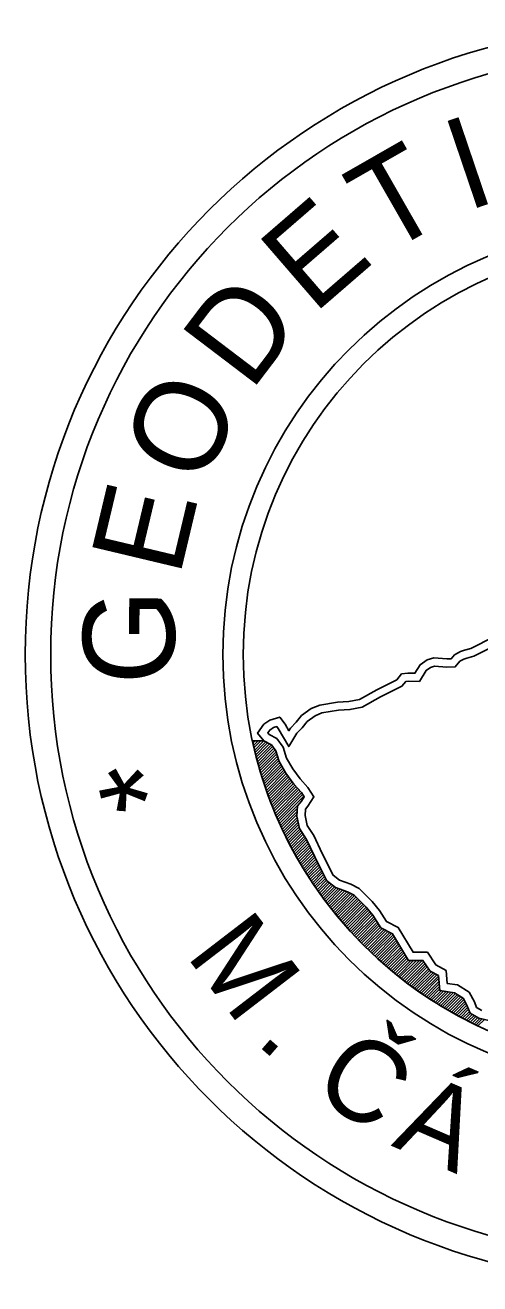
# Model space of a CAD drawing. Extents: x -820819 to -820609, y -1070301 to -1070004.
# Drawn here: x -820684.45 to -820678.53, y -1070186.61 to -1070170.22 of the extents above; entities that cross this region are included whole.
import ezdxf

# ---------------------------------------------------------------- set-up
doc = ezdxf.new("R2010")
doc.units = 0
doc.layers.add('Vrstva 63', color=7, linetype='Continuous')

msp = doc.modelspace()

# ---------------------------------------------------------------- linework, layer by layer
at = {"layer": 'Vrstva 63'}
for p, q in [((-820681.342, -1070179.542), (-820681.491, -1070179.541)), ((-820681.342, -1070179.542), (-820681.491, -1070179.541)), ((-820681.491, -1070179.541), (-820681.49, -1070179.541)), ((-820681.484, -1070179.572), (-820681.453, -1070179.541)), ((-820681.477, -1070179.603), (-820681.416, -1070179.541)), ((-820681.47, -1070179.633), (-820681.379, -1070179.542)), ((-820681.463, -1070179.664), (-820681.341, -1070179.542)), ((-820681.456, -1070179.694), (-820681.317, -1070179.555)), ((-820681.448, -1070179.724), (-820681.292, -1070179.568)), ((-820681.441, -1070179.754), (-820681.268, -1070179.581)), ((-820681.433, -1070179.784), (-820681.243, -1070179.594)), ((-820681.425, -1070179.813), (-820681.227, -1070179.615)), ((-820681.417, -1070179.843), (-820681.211, -1070179.637)), ((-820681.409, -1070179.872), (-820681.194, -1070179.658)), ((-820681.4, -1070179.901), (-820681.181, -1070179.683)), ((-820681.392, -1070179.931), (-820681.173, -1070179.711)), ((-820681.383, -1070179.959), (-820681.164, -1070179.74)), ((-820681.374, -1070179.988), (-820681.155, -1070179.769)), ((-820681.365, -1070180.017), (-820681.146, -1070179.798)), ((-820681.356, -1070180.046), (-820681.134, -1070179.823)), ((-820681.347, -1070180.074), (-820681.12, -1070179.847)), ((-820681.338, -1070180.102), (-820681.106, -1070179.871)), ((-820681.329, -1070180.13), (-820681.092, -1070179.894)), ((-820681.319, -1070180.158), (-820681.078, -1070179.918)), ((-820681.309, -1070180.186), (-820681.064, -1070179.941)), ((-820681.299, -1070180.214), (-820681.05, -1070179.965)), ((-820681.29, -1070180.242), (-820681.035, -1070179.987)), ((-820681.279, -1070180.269), (-820681.019, -1070180.009)), ((-820681.269, -1070180.297), (-820681.004, -1070180.031)), ((-820681.259, -1070180.324), (-820680.988, -1070180.053)), ((-820681.249, -1070180.351), (-820680.973, -1070180.075)), ((-820681.238, -1070180.378), (-820680.957, -1070180.097)), ((-820681.227, -1070180.405), (-820680.94, -1070180.118)), ((-820681.216, -1070180.432), (-820680.922, -1070180.137)), ((-820681.206, -1070180.458), (-820680.904, -1070180.157)), ((-820681.195, -1070180.485), (-820680.886, -1070180.176)), ((-820681.183, -1070180.511), (-820680.868, -1070180.196)), ((-820681.172, -1070180.538), (-820680.85, -1070180.216)), ((-820681.161, -1070180.564), (-820680.836, -1070180.239)), ((-820681.149, -1070180.59), (-820680.821, -1070180.262)), ((-820681.138, -1070180.616), (-820680.878, -1070180.356)), ((-820681.126, -1070180.642), (-820680.906, -1070180.422)), ((-820681.114, -1070180.667), (-820680.908, -1070180.462)), ((-820681.102, -1070180.693), (-820680.91, -1070180.501)), ((-820681.09, -1070180.719), (-820680.908, -1070180.537)), ((-820681.078, -1070180.744), (-820680.902, -1070180.568)), ((-820681.066, -1070180.769), (-820680.895, -1070180.599)), ((-820681.053, -1070180.794), (-820680.889, -1070180.63)), ((-820681.041, -1070180.82), (-820680.882, -1070180.661)), ((-820681.028, -1070180.845), (-820680.874, -1070180.69)), ((-820681.015, -1070180.869), (-820680.859, -1070180.713)), ((-820681.002, -1070180.894), (-820680.844, -1070180.735)), ((-820680.99, -1070180.919), (-820680.829, -1070180.758)), ((-820680.976, -1070180.943), (-820680.814, -1070180.781)), ((-820680.963, -1070180.968), (-820680.799, -1070180.804)), ((-820680.95, -1070180.992), (-820680.784, -1070180.826)), ((-820680.937, -1070181.016), (-820680.772, -1070180.852)), ((-820680.923, -1070181.04), (-820680.76, -1070180.877)), ((-820680.91, -1070181.064), (-820680.748, -1070180.903)), ((-820680.896, -1070181.088), (-820680.736, -1070180.928)), ((-820680.882, -1070181.112), (-820680.724, -1070180.954)), ((-820680.868, -1070181.136), (-820680.712, -1070180.979)), ((-820680.854, -1070181.159), (-820680.7, -1070181.005)), ((-820680.84, -1070181.183), (-820680.688, -1070181.031)), ((-820680.826, -1070181.206), (-820680.676, -1070181.056)), ((-820680.812, -1070181.229), (-820680.663, -1070181.081)), ((-820680.797, -1070181.253), (-820680.651, -1070181.106)), ((-820680.783, -1070181.276), (-820680.638, -1070181.131)), ((-820680.768, -1070181.299), (-820680.626, -1070181.156)), ((-820680.754, -1070181.322), (-820680.613, -1070181.181)), ((-820680.739, -1070181.344), (-820680.601, -1070181.207)), ((-820680.724, -1070181.367), (-820680.588, -1070181.232)), ((-820680.709, -1070181.39), (-820680.576, -1070181.257)), ((-820680.694, -1070181.412), (-820680.563, -1070181.282)), ((-820680.679, -1070181.435), (-820680.551, -1070181.307)), ((-820680.663, -1070181.457), (-820680.539, -1070181.332)), ((-820680.648, -1070181.479), (-820680.526, -1070181.357)), ((-820680.632, -1070181.501), (-820680.506, -1070181.375)), ((-820680.617, -1070181.523), (-820680.485, -1070181.391)), ((-820680.601, -1070181.545), (-820680.464, -1070181.407)), ((-820680.585, -1070181.567), (-820680.442, -1070181.424)), ((-820680.57, -1070181.589), (-820680.421, -1070181.44)), ((-820680.554, -1070181.61), (-820680.398, -1070181.455)), ((-820680.537, -1070181.632), (-820680.37, -1070181.464)), ((-820680.521, -1070181.653), (-820680.342, -1070181.474)), ((-820680.505, -1070181.674), (-820680.314, -1070181.483)), ((-820680.489, -1070181.696), (-820680.286, -1070181.493)), ((-820680.472, -1070181.717), (-820680.258, -1070181.503)), ((-820680.456, -1070181.738), (-820680.232, -1070181.514)), ((-820680.439, -1070181.759), (-820680.208, -1070181.527)), ((-820680.422, -1070181.78), (-820680.183, -1070181.54)), ((-820680.405, -1070181.8), (-820680.159, -1070181.554)), ((-820680.389, -1070181.821), (-820680.14, -1070181.573)), ((-820680.372, -1070181.841), (-820680.122, -1070181.592)), ((-820680.354, -1070181.862), (-820680.103, -1070181.611)), ((-820680.337, -1070181.882), (-820680.084, -1070181.63)), ((-820680.32, -1070181.903), (-820680.066, -1070181.648)), ((-820680.303, -1070181.923), (-820680.047, -1070181.667)), ((-820680.285, -1070181.943), (-820680.029, -1070181.686)), ((-820680.267, -1070181.963), (-820680.01, -1070181.705)), ((-820680.25, -1070181.983), (-820679.993, -1070181.726)), ((-820680.232, -1070182.003), (-820679.976, -1070181.746)), ((-820680.214, -1070182.022), (-820679.959, -1070181.767)), ((-820680.196, -1070182.042), (-820679.942, -1070181.787)), ((-820680.178, -1070182.061), (-820679.925, -1070181.808)), ((-820680.16, -1070182.081), (-820679.91, -1070181.831)), ((-820680.142, -1070182.1), (-820679.895, -1070181.854)), ((-820680.123, -1070182.119), (-820679.881, -1070181.877)), ((-820680.105, -1070182.139), (-820679.866, -1070181.9)), ((-820680.086, -1070182.158), (-820679.852, -1070181.923)), ((-820680.068, -1070182.177), (-820679.837, -1070181.946)), ((-820680.049, -1070182.196), (-820679.823, -1070181.969)), ((-820680.03, -1070182.214), (-820679.801, -1070181.985)), ((-820680.011, -1070182.233), (-820679.776, -1070181.998)), ((-820679.992, -1070182.252), (-820679.751, -1070182.01)), ((-820679.973, -1070182.27), (-820679.726, -1070182.022)), ((-820679.954, -1070182.288), (-820679.7, -1070182.035)), ((-820679.935, -1070182.307), (-820679.675, -1070182.047)), ((-820679.916, -1070182.325), (-820679.657, -1070182.066)), ((-820679.896, -1070182.343), (-820679.643, -1070182.09)), ((-820679.877, -1070182.361), (-820679.629, -1070182.113)), ((-820679.857, -1070182.379), (-820679.615, -1070182.137)), ((-820679.837, -1070182.397), (-820679.601, -1070182.16)), ((-820679.817, -1070182.415), (-820679.587, -1070182.184)), ((-820679.797, -1070182.432), (-820679.573, -1070182.207)), ((-820679.777, -1070182.45), (-820679.558, -1070182.231)), ((-820679.757, -1070182.467), (-820679.544, -1070182.255)), ((-820679.737, -1070182.485), (-820679.53, -1070182.278)), ((-820679.717, -1070182.502), (-820679.516, -1070182.302)), ((-820679.696, -1070182.519), (-820679.502, -1070182.325)), ((-820679.676, -1070182.536), (-820679.488, -1070182.349)), ((-820679.655, -1070182.553), (-820679.474, -1070182.372)), ((-820679.635, -1070182.57), (-820679.46, -1070182.396)), ((-820679.614, -1070182.587), (-820679.428, -1070182.401)), ((-820679.593, -1070182.604), (-820679.39, -1070182.401)), ((-820679.572, -1070182.62), (-820679.352, -1070182.401)), ((-820679.551, -1070182.637), (-820679.315, -1070182.4)), ((-820679.53, -1070182.653), (-820679.277, -1070182.4)), ((-820679.509, -1070182.67), (-820679.256, -1070182.417)), ((-820679.487, -1070182.686), (-820679.241, -1070182.44)), ((-820679.466, -1070182.702), (-820679.226, -1070182.463)), ((-820679.444, -1070182.718), (-820679.212, -1070182.485)), ((-820679.423, -1070182.734), (-820679.197, -1070182.508)), ((-820679.401, -1070182.75), (-820679.182, -1070182.531)), ((-820679.379, -1070182.766), (-820679.161, -1070182.547)), ((-820679.357, -1070182.781), (-820679.137, -1070182.561)), ((-820679.335, -1070182.797), (-820679.112, -1070182.574)), ((-820679.313, -1070182.812), (-820679.088, -1070182.587)), ((-820679.291, -1070182.828), (-820679.067, -1070182.604)), ((-820679.269, -1070182.843), (-820679.064, -1070182.638)), ((-820679.246, -1070182.858), (-820679.061, -1070182.673)), ((-820679.224, -1070182.873), (-820679.058, -1070182.707)), ((-820679.201, -1070182.888), (-820679.055, -1070182.742)), ((-820679.178, -1070182.903), (-820679.051, -1070182.776)), ((-820679.156, -1070182.918), (-820679.032, -1070182.795)), ((-820679.133, -1070182.933), (-820679, -1070182.8)), ((-820679.11, -1070182.947), (-820678.967, -1070182.805)), ((-820679.087, -1070182.962), (-820678.935, -1070182.81)), ((-820679.063, -1070182.976), (-820678.902, -1070182.815)), ((-820679.04, -1070182.99), (-820678.87, -1070182.82)), ((-820679.017, -1070183.004), (-820678.843, -1070182.831)), ((-820678.993, -1070183.019), (-820678.82, -1070182.845)), ((-820678.97, -1070183.033), (-820678.797, -1070182.859)), ((-820678.946, -1070183.046), (-820678.773, -1070182.874)), ((-820678.922, -1070183.06), (-820678.75, -1070182.888)), ((-820678.898, -1070183.074), (-820678.735, -1070182.91)), ((-820678.874, -1070183.087), (-820678.722, -1070182.935)), ((-820678.85, -1070183.101), (-820678.709, -1070182.959)), ((-820678.826, -1070183.114), (-820678.696, -1070182.984)), ((-820678.801, -1070183.127), (-820678.685, -1070183.01)), ((-820678.777, -1070183.141), (-820678.674, -1070183.037)), ((-820678.752, -1070183.154), (-820678.663, -1070183.064)), ((-820678.728, -1070183.166), (-820678.65, -1070183.089)), ((-820678.703, -1070183.179), (-820678.626, -1070183.103)), ((-820678.678, -1070183.192), (-820678.603, -1070183.116)), ((-820678.653, -1070183.205), (-820678.579, -1070183.13)), ((-820678.628, -1070183.217), (-820678.555, -1070183.144)), ((-820678.603, -1070183.229), (-820678.528, -1070183.155)), ((-820678.578, -1070183.242), (-820678.498, -1070183.162)), ((-820678.552, -1070183.254), (-820678.467, -1070183.169))]:
    msp.add_line(p, q, dxfattribs=at)
for points in [[(-820678.347, -1070178.187), (-820678.646, -1070178.337), (-820678.728, -1070178.361), (-820678.779, -1070178.378), (-820678.859, -1070178.421), (-820678.9, -1070178.471), (-820678.956, -1070178.473), (-820679.127, -1070178.461), (-820679.215, -1070178.486), (-820679.304, -1070178.549), (-820679.374, -1070178.659), (-820679.464, -1070178.659), (-820679.547, -1070178.666), (-820679.61, -1070178.746), (-820679.871, -1070178.875), (-820680.097, -1070179), (-820680.235, -1070179.027), (-820680.382, -1070179.036), (-820680.614, -1070179.074), (-820680.727, -1070179.12), (-820680.85, -1070179.212), (-820680.922, -1070179.299), (-820680.995, -1070179.375), (-820681.015, -1070179.409), (-820681.065, -1070179.323), (-820681.134, -1070179.23), (-820681.265, -1070179.272), (-820681.341, -1070179.322), (-820681.423, -1070179.439), (-820681.342, -1070179.542), (-820681.243, -1070179.594), (-820681.185, -1070179.67), (-820681.143, -1070179.81), (-820681.053, -1070179.961), (-820680.952, -1070180.104), (-820680.853, -1070180.212), (-820680.816, -1070180.269), (-820680.852, -1070180.327), (-820680.904, -1070180.386), (-820680.912, -1070180.522), (-820680.878, -1070180.684), (-820680.785, -1070180.826), (-820680.677, -1070181.053), (-820680.524, -1070181.361), (-820680.406, -1070181.452), (-820680.251, -1070181.505), (-820680.163, -1070181.55), (-820680.01, -1070181.705), (-820679.921, -1070181.812), (-820679.818, -1070181.977), (-820679.665, -1070182.052), (-820679.457, -1070182.401), (-820679.268, -1070182.4), (-820679.176, -1070182.539), (-820679.068, -1070182.598), (-820679.05, -1070182.792), (-820678.858, -1070182.822), (-820678.745, -1070182.891), (-820678.695, -1070182.984), (-820678.653, -1070183.087), (-820678.542, -1070183.151), (-820678.411, -1070183.182)], [(-820678.503, -1070183.051), (-820678.569, -1070183.013), (-820678.599, -1070182.939), (-820678.665, -1070182.816), (-820678.82, -1070182.72), (-820678.952, -1070182.7), (-820678.967, -1070182.533), (-820679.102, -1070182.458), (-820679.211, -1070182.294), (-820679.397, -1070182.295), (-820679.59, -1070181.97), (-820679.744, -1070181.895), (-820679.835, -1070181.75), (-820679.932, -1070181.633), (-820680.1, -1070181.463), (-820680.21, -1070181.407), (-820680.355, -1070181.357), (-820680.44, -1070181.292), (-820680.582, -1070181.006), (-820680.692, -1070180.774), (-820680.778, -1070180.642), (-820680.805, -1070180.514), (-820680.8, -1070180.429), (-820680.767, -1070180.391), (-820680.69, -1070180.268), (-820680.768, -1070180.147), (-820680.869, -1070180.037), (-820680.963, -1070179.903), (-820681.045, -1070179.766), (-820681.089, -1070179.621), (-820681.173, -1070179.511), (-820681.272, -1070179.458), (-820681.29, -1070179.435), (-820681.265, -1070179.4), (-820681.218, -1070179.368), (-820681.174, -1070179.354), (-820681.154, -1070179.381), (-820681.018, -1070179.616), (-820680.91, -1070179.44), (-820680.843, -1070179.369), (-820680.776, -1070179.29), (-820680.674, -1070179.213), (-820680.585, -1070179.177), (-820680.37, -1070179.142), (-820680.221, -1070179.133), (-820680.06, -1070179.101), (-820679.822, -1070178.969), (-820679.542, -1070178.83), (-820679.492, -1070178.768), (-820679.46, -1070178.765), (-820679.315, -1070178.766), (-820679.225, -1070178.623), (-820679.169, -1070178.583), (-820679.116, -1070178.568), (-820678.958, -1070178.579), (-820678.848, -1070178.576), (-820678.79, -1070178.504), (-820678.737, -1070178.476), (-820678.696, -1070178.463), (-820678.607, -1070178.437), (-820678.31, -1070178.288)], [(-820678.411, -1070183.182), (-820678.542, -1070183.151), (-820678.653, -1070183.087), (-820678.695, -1070182.984), (-820678.745, -1070182.891), (-820678.858, -1070182.822), (-820679.05, -1070182.792), (-820679.068, -1070182.598), (-820679.176, -1070182.539), (-820679.268, -1070182.4), (-820679.457, -1070182.401), (-820679.665, -1070182.052), (-820679.818, -1070181.977), (-820679.921, -1070181.812), (-820680.01, -1070181.705), (-820680.163, -1070181.55), (-820680.251, -1070181.505), (-820680.406, -1070181.452), (-820680.524, -1070181.361), (-820680.677, -1070181.053), (-820680.785, -1070180.826), (-820680.878, -1070180.684), (-820680.912, -1070180.522), (-820680.904, -1070180.386), (-820680.852, -1070180.327), (-820680.816, -1070180.269), (-820680.853, -1070180.212), (-820680.952, -1070180.104), (-820681.053, -1070179.961), (-820681.143, -1070179.81), (-820681.185, -1070179.67), (-820681.243, -1070179.594), (-820681.342, -1070179.542)]]:
    msp.add_lwpolyline(points, dxfattribs=at)
for radius in [8.197, 7.865, 7.865, 5.622, 5.622, 5.356]:
    msp.add_circle((-820676.254, -1070178.416), radius, dxfattribs=at)
msp.add_arc((-820676.254, -1070178.416), 5.356, 192.1248, 329.9318, dxfattribs=at)

# ---------------------------------------------------------------- texts
for s, height, rotation, p in [('I', 1.196, 18.7306, (-820678.702, -1070172.645)), ('T', 1.196, 29.797, (-820679.764, -1070173.223)), ('E', 1.196, 40.8634, (-820680.695, -1070173.993)), ('D', 1.196, 52.7843, (-820681.513, -1070175.005)), ('O', 1.196, 65.5492, (-820682.136, -1070176.252)), ('E', 1.196, 76.6156, (-820682.442, -1070177.421)), ('G', 1.196, 89.3804, (-820682.509, -1070178.813)), ('*', 1.196, 103.0104, (-820682.239, -1070180.276)), ('M', 1.063, 307.5302, (-820682.368, -1070182.332)), ('Č', 1.063, 326.6696, (-820680.746, -1070184.121)), ('.', 1.063, 319.0138, (-820681.466, -1070183.471)), ('Á', 1.063, 336.6266, (-820679.692, -1070184.811))]:
    msp.add_text(s, height=height, rotation=rotation, dxfattribs=at).set_placement(p)

doc.saveas('drawing.dxf')
